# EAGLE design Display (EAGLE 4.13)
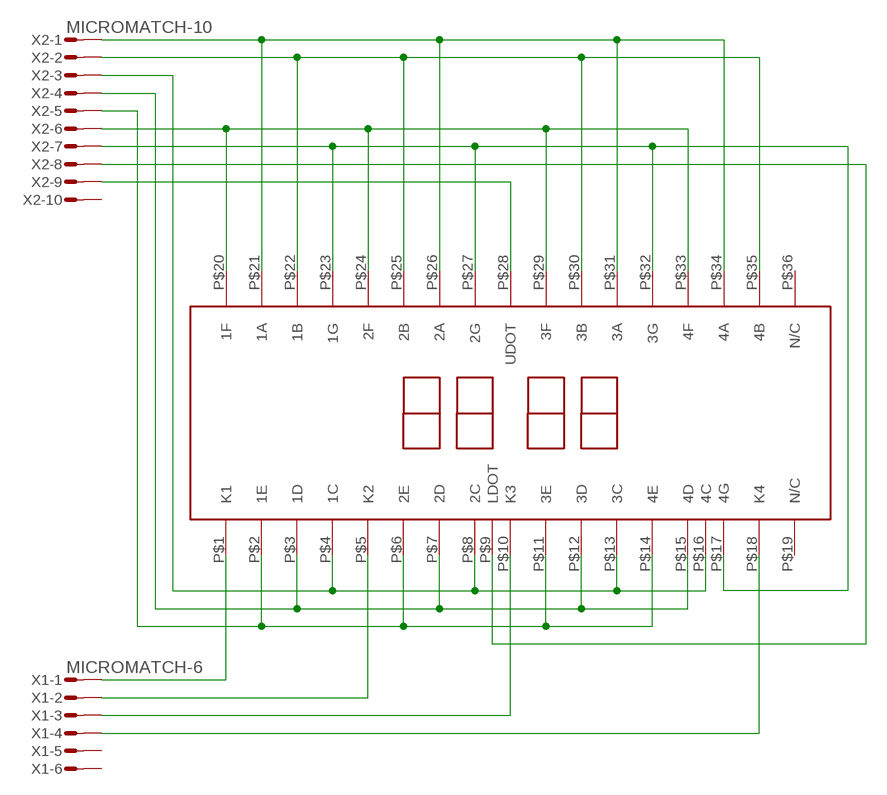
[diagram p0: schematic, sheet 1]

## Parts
U$1  4DIGITLED  [4DIGITLED-DISPLAY]
X1  MICROMATCH-6  [MICROMATCH-6]
X2  MICROMATCH-10  [MICROMATCH-10]

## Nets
N$1: U$1.P$1(K1) X1.1
N$2: U$1.P$5(K2) X1.2
N$3: U$1.P$10(K3) X1.3
N$4: U$1.P$18(K4) X1.4
N$5: U$1.P$21(1A) U$1.P$26(2A) U$1.P$31(3A) U$1.P$34(4A) X2.1
N$6: U$1.P$22(1B) U$1.P$25(2B) U$1.P$30(3B) U$1.P$35(4B) X2.2
N$7: U$1.P$4(1C) U$1.P$8(2C) U$1.P$13(3C) U$1.P$16(4C) X2.3
N$8: U$1.P$3(1D) U$1.P$7(2D) U$1.P$12(3D) U$1.P$15(4D) X2.4
N$9: U$1.P$2(1E) U$1.P$6(2E) U$1.P$11(3E) U$1.P$14(4E) X2.5
N$10: U$1.P$20(1F) U$1.P$24(2F) U$1.P$29(3F) U$1.P$33(4F) X2.6
N$11: U$1.P$17(4G) U$1.P$23(1G) U$1.P$27(2G) U$1.P$32(3G) X2.7
N$12: U$1.P$9(LDOT) X2.8
N$13: U$1.P$28(UDOT) X2.9
Unconnected: U$1.P$19(N/C) U$1.P$36(N/C) X1.5 X1.6 X2.10

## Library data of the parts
U$1 = LED-Display:4DIGITLED
X1 = con-amp-micromatch:MICROMATCH-6: MicroMaTch 6 7-215464-6 / 0-215464-6 Drawing Number C-215464 DDEController.pdf
X2 = con-amp-micromatch:MICROMATCH-10: MicroMaTch 10 8-215464-0 / 1-215464-0 Drawing Number C-215464 DDEController.pdf

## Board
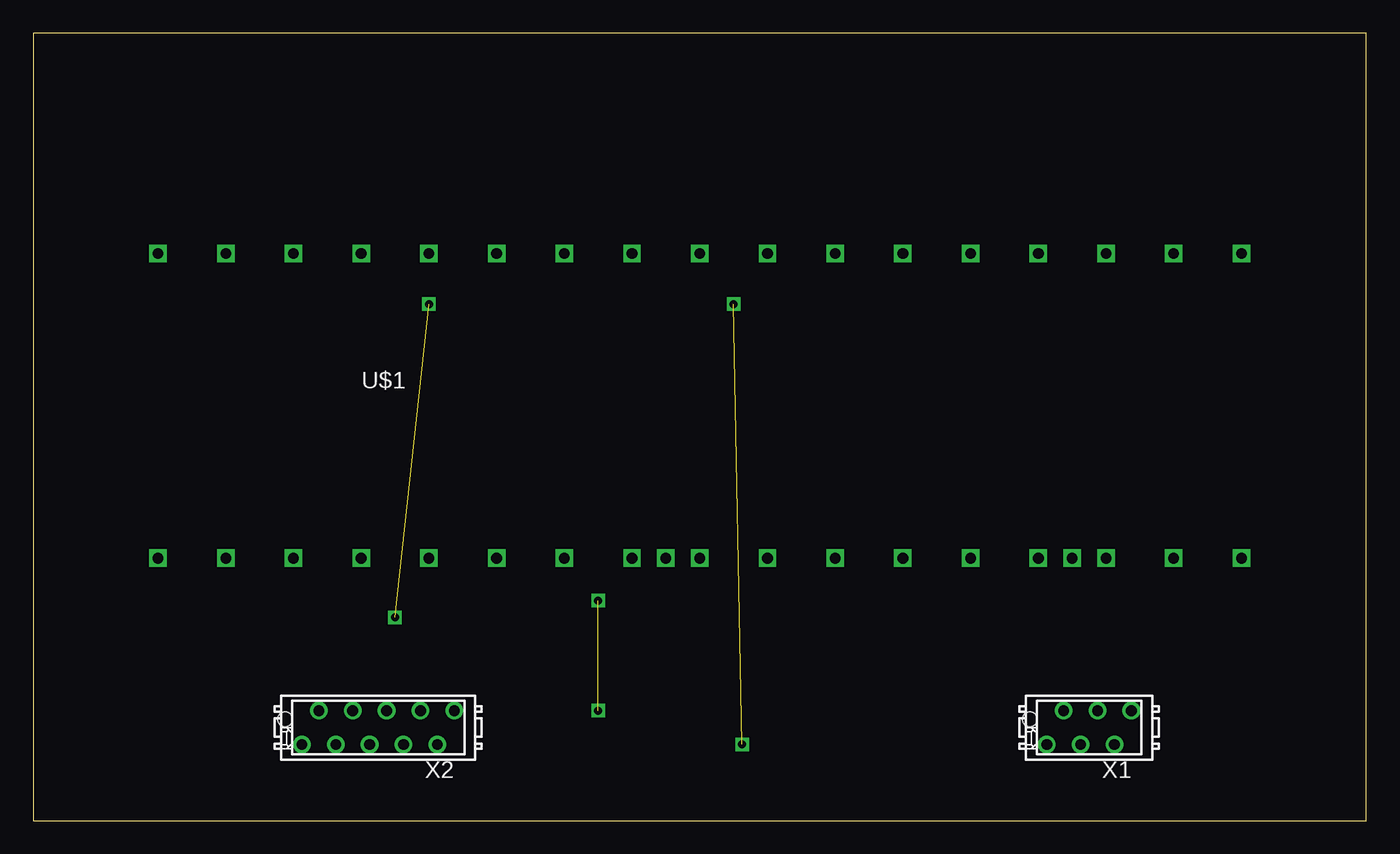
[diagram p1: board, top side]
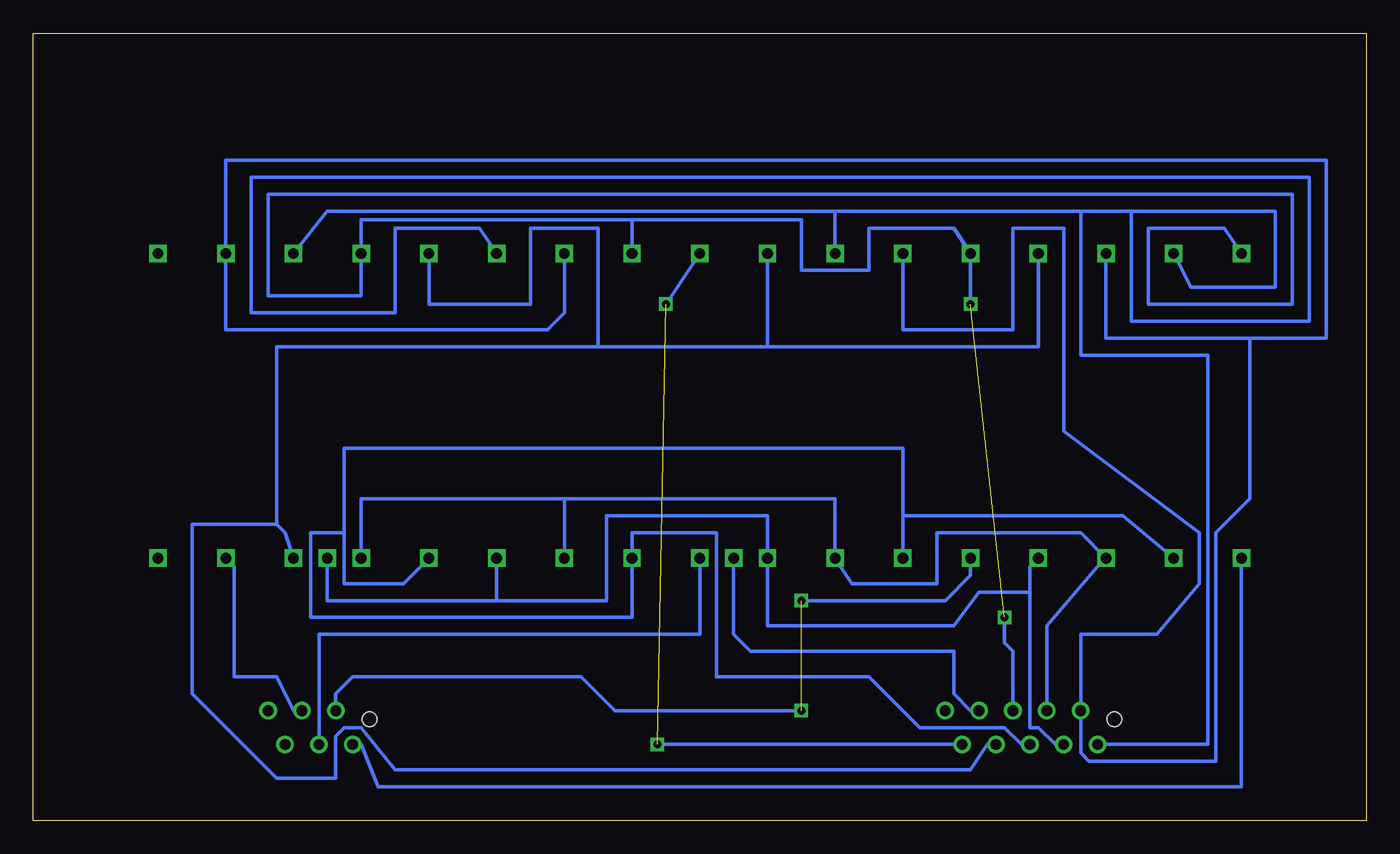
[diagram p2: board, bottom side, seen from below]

Size 100 x 59.05 mm. Coordinates in mm from the lower left corner, seen from the top.
Outline: 0,0 100,0 100,59.05 0,59.05 0,0
Copper layers (1*16): Top 0.035mm / dielectric 1.5mm / Bottom 0.035mm
Design rules "default": minimum track width 10mil, minimum drill 24mil, track to track 8mil, track to pad 8mil, pad to pad 8mil, via to via 8mil, smd to smd 8mil, copper to edge 40mil, drill to drill 8mil, minimum pad ring 10mil, minimum via ring 8mil, stop-mask expansion 4mil, vias tented up to drill 0mil, thermal gap 10mil
Holes 1.1 mm at 18.88,7.62 74.77,7.62

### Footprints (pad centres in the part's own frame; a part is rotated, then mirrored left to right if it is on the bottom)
4DIGITLED-DISPLAY = drill 0.8 square: P$1 -33.02,-12.7; P$2 -27.94,-12.7; P$3 -22.86,-12.7; P$4 -17.78,-12.7; P$5 -12.7,-12.7; P$6 -7.62,-12.7; P$7 -2.54,-12.7; P$8 2.54,-12.7; P$9 5.08,-12.7; P$10 7.62,-12.7; P$11 12.7,-12.7; P$12 17.78,-12.7; P$13 22.86,-12.7; P$14 27.94,-12.7; P$15 33.02,-12.7; P$16 35.56,-12.7; P$17 38.1,-12.7; P$18 43.18,-12.7; P$19 48.26,-12.7; P$20 -33.02,10.16; P$21 -27.94,10.16; P$22 -22.86,10.16; P$23 -17.78,10.16; P$24 -12.7,10.16; P$25 -7.62,10.16; P$26 -2.54,10.16; P$27 2.54,10.16; P$28 7.62,10.16; P$29 12.7,10.16; P$30 17.78,10.16; P$31 22.86,10.16; P$32 27.94,10.16; P$33 33.02,10.16; P$34 38.1,10.16; P$35 43.18,10.16; P$36 48.26,10.16
MICROMATCH-6 = drill 0.813 round: 1 3.175,1.27; 2 1.905,-1.27; 3 0.635,1.27; 4 -0.635,-1.27; 5 -1.905,1.27; 6 -3.175,-1.27
MICROMATCH-10 = drill 0.813 round: 1 5.715,1.27; 2 4.445,-1.27; 3 3.175,1.27; 4 1.905,-1.27; 5 0.635,1.27; 6 -0.635,-1.27; 7 -1.905,1.27; 8 -3.175,-1.27; 9 -4.445,1.27; 10 -5.715,-1.27

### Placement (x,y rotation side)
U$1  42.38,32.38 0 top
X1  79.21,6.98 180 top
X2  25.87,6.98 180 top

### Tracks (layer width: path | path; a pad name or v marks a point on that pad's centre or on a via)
N$1
  Bottom 0.254: U$1.P$1 9.36,2.54 74.13,2.54 75.4,5.71 X1.1
N$2  (1 unrouted)
  Bottom 0.254: U$1.P$5 29.68,18.41 31.58,16.5 42.38,16.5 | X1.2 77.3,9.52 76.03,10.79 58.89,10.79 56.35,8.25 42.38,8.25
N$3
  Bottom 0.254: U$1.P$10 50,13.97 78.58,13.97 X1.3
N$4
  Bottom 0.254: U$1.P$18 84.92,19.04 84.92,10.79 81.75,10.79 80.48,8.25 X1.4
N$5
  Bottom 0.254: 21.42,45.72 39.84,45.72 | 21.42,45.72 17.61,45.72 | 17.61,45.72 6.82,45.72 6.82,40 13.17,40 U$1.P$21 | 17.61,45.72 17.61,37.46 4.28,37.46 4.28,48.26 83.66,48.26 83.66,38.1 72.86,38.1 72.86,44.45 66.51,44.45 U$1.P$31 | 39.84,45.72 77.94,45.72 U$1.P$34 | U$1.P$26 39.84,45.72 | 21.42,45.72 21.42,34.92 11.9,34.92 11.9,5.71 X2.1
N$6
  Bottom 0.254: U$1.P$30 60.16,38.1 61.43,36.83 85.56,36.83 U$1.P$35 85.56,49.53 3.01,49.53 3.01,36.19 8.73,36.19 | 8.73,36.19 19.52,36.19 U$1.P$22 | 8.73,36.19 8.73,24.12 11.27,21.58 11.27,4.44 20.79,4.44 21.42,5.08 X2.2 21.42,13.97 15.71,13.97 12.54,17.77 12.54,21.58 22.7,29.2 22.7,44.45 26.5,44.45 26.5,36.83 34.76,36.83 U$1.P$25
N$7
  Bottom 0.254: 65.24,16.5 77.94,16.5 U$1.P$16 | 25.23,17.14 25.23,6.98 24.6,6.98 23.33,5.71 X2.3 | 25.23,17.14 25.23,19.04 U$1.P$4 | 25.23,17.14 29.04,17.14 30.95,14.6 44.92,14.6 U$1.P$8 44.92,22.86 56.98,22.86 56.98,16.5 65.24,16.5 | 65.24,16.5 U$1.P$13
N$8
  Bottom 0.254: X2.4 23.96,14.6 20.15,19.04 U$1.P$3 21.42,21.58 32.22,21.58 32.22,17.77 38.57,17.77 U$1.P$7 39.84,24.12 60.16,24.12 | 60.16,24.12 U$1.P$12 | 60.16,24.12 75.4,24.12 U$1.P$15
N$9
  Bottom 0.254: X2.5 25.87,5.71 27.14,6.98 33.49,6.98 37.3,10.79 48.73,10.79 48.73,21.58 55.08,21.58 U$1.P$11 55.08,15.24 79.21,15.24 79.21,21.58 76.67,21.58 | U$1.P$2 18.25,22.86 34.76,22.86 U$1.P$6 34.76,27.93 76.67,27.93 76.67,21.58 | 76.67,21.58 76.67,17.77 72.22,17.77 U$1.P$14
N$10  (1 unrouted)
  Bottom 0.254: 55.08,45.08 42.38,45.08 42.38,41.27 37.3,41.27 37.3,44.45 30.95,44.45 U$1.P$24 29.68,38.73 | U$1.P$20 10.63,44.45 16.34,44.45 16.34,38.73 5.55,38.73 5.55,46.98 82.39,46.98 82.39,39.37 75.4,39.37 U$1.P$33 75.4,45.08 55.08,45.08 | 55.08,45.08 U$1.P$29 | X2.6 26.5,12.7 27.14,13.33 27.14,15.24
N$11
  Bottom 0.254: 81.75,22.22 81.75,35.55 57.62,35.55 | 81.75,22.22 81.11,21.58 U$1.P$17 | 57.62,35.55 44.92,35.55 | 44.92,35.55 U$1.P$27 | 44.92,35.55 24.6,35.55 U$1.P$23 | 57.62,35.55 57.62,44.45 62.7,44.45 62.7,38.73 70.32,38.73 U$1.P$32 | 81.75,22.22 88.1,22.22 88.1,9.52 81.75,3.17 77.3,3.17 77.3,6.34 76.67,6.98 75.4,6.98 72.86,3.8 29.68,3.8 28.41,5.71 X2.7
N$12
  Bottom 0.254: U$1.P$9 47.46,13.97 46.19,12.7 30.95,12.7 30.95,9.52 29.68,8.25 X2.8
N$13  (1 unrouted)
  Bottom 0.254: 52.54,38.73 U$1.P$28 | X2.9 53.17,5.71
N$14  (via drill 0.6)
  other vias: 29.68,38.73
N$15  (via drill 0.6)
  other vias: 27.14,15.24
N$16  (via drill 0.6)
  other vias: 42.38,16.5
N$17  (via drill 0.6)
  other vias: 42.38,8.25
N$18  (via drill 0.6)
  other vias: 52.54,38.73
N$19  (via drill 0.6)
  other vias: 53.17,5.71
